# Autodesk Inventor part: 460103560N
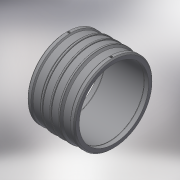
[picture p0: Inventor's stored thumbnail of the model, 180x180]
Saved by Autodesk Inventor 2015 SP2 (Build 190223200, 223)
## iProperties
Created: 2017-06
Part Number: 460103560N
Material: Generic
Description: PLASSON LIGHTFIT COUPLER 560N
Document SubType Name: Modeling
Designer: KIM
Mass: 17859.4 g
Surface Area: 15499.5 cm^2
Volume: 17859.4 cm^3
Density: 1 g/cm^3
Appearance: Default
Author: KIM
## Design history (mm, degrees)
derived "460103.ipt"
feature "Solid1::460103.ipt"
tag "TaggingFeature1"
body "Solid1"
other parameters: "d13" = 376, "d14" = 17.6296, "d15" = 188, "d16" = 188, "d19" = 3.52592, "d20" = 168 deg, "d22" = 618, "d23" = 628, "d24" = 599.46, "d25" = 135 deg, "d26" = 150.4, "d27" = 135 deg, "d29" = 309, "d35" = 15, "d39" = 0, "d40" = 4, "d41" = 14, "d42" = 0, "d43" = 135 deg, "d44" = 41.36, "d45" = 15.04, "d46" = 15.04, "d47" = 15.04, "d48" = 615.44, "d49" = 628, "d50" = 3.14, "d51" = 6, "d52" = 0, "L_" = 376, "L_1" = 188, "D_" = 628, "A_" = 309, "d_2" = 12
